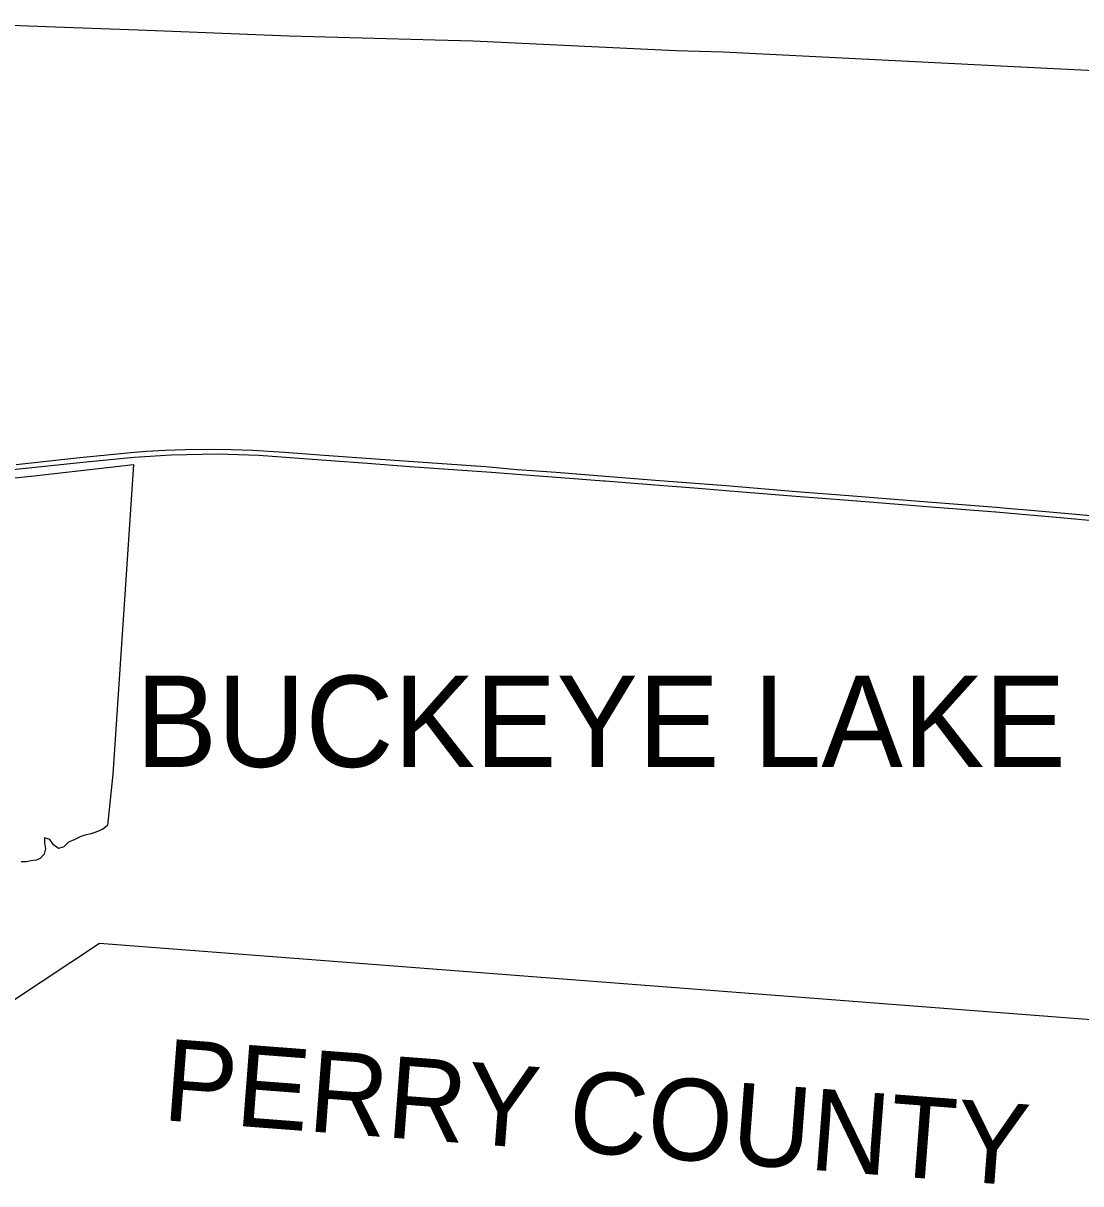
# Model space of a CAD drawing. Extents: x 1853412 to 2125412, y 78841 to 855418.
# Drawn here: x 1977959 to 1990925, y 700118 to 714345 of the extents above; entities that cross this region are included whole.
import ezdxf

# ---------------------------------------------------------------- set-up
doc = ezdxf.new("R2010")
doc.units = 0
for name, color, linetype in [('GM_X_Corporation', 7, 'Continuous'), ('GM_X_Corporation_Text', 7, 'Continuous'), ('GM_X_County', 7, 'Continuous'), ('GM_X_County_Text', 7, 'Continuous'), ('GM_X_US_Route', 7, 'Continuous'), ('UT_P_Electric', 7, 'Continuous')]:
    doc.layers.add(name, color=color, linetype=linetype)

msp = doc.modelspace()

# ---------------------------------------------------------------- linework, layer by layer
at = {"layer": 'GM_X_Corporation'}
msp.add_lwpolyline([(1976528, 708641), (1978057, 708794), (1979311, 708937), (1979058, 705139), (1978993, 704509), (1978936, 704465), (1978868, 704437), (1978792, 704409), (1978716, 704390), (1978664, 704374), (1978590, 704338), (1978514, 704306), (1978456, 704250), (1978390, 704227), (1978330, 704273), (1978286, 704337), (1978220, 704359), (1978218, 704297), (1978234, 704225), (1978216, 704159), (1978167, 704107), (1978117, 704085), (1978052, 704076), (1978000, 704064), (1977932, 704064)], dxfattribs=at)
at = {"layer": 'GM_X_County'}
msp.add_lwpolyline([(1991425, 702099), (1978895, 703062), (1976042, 701178), (1970119, 701527), (1969837, 701546), (1969206, 701588), (1968963, 701604), (1967601, 701695), (1967104, 701729), (1966807, 701761), (1966648, 701765), (1966605, 701765), (1965937, 701808), (1964838, 701880), (1963273, 701974), (1962141, 702051), (1961404, 702092), (1960067, 702149), (1959325, 702195), (1956245, 702403), (1956176, 702427), (1945541, 702974)], dxfattribs=at)
at = {"layer": 'GM_X_US_Route'}
for p, q in [((1990352, 713802), (1990516, 713794)), ((1990516, 713794), (1991173, 713761))]:
    msp.add_line(p, q, dxfattribs=at)
for points in [[(1977155, 714345), (1977251, 714341), (1978575, 714294), (1979368, 714263)], [(1979368, 714263), (1979686, 714252), (1981219, 714192), (1983008, 714140), (1983474, 714129), (1985961, 714010), (1986539, 713992), (1990352, 713802)]]:
    msp.add_lwpolyline(points, dxfattribs=at)
at = {"layer": 'UT_P_Electric'}
for p, q in [((1984497, 708781), (1985078, 708737)), ((1985701, 708688), (1986186, 708649))]:
    msp.add_line(p, q, dxfattribs=at)
for points in [[(1977266, 708814), (1977909, 708884), (1978729, 708968), (1979319, 709027), (1979773, 709055), (1980339, 709065), (1980848, 709048), (1981728, 708986), (1982178, 708950), (1982699, 708912)], [(1977873, 708936), (1978652, 709022), (1979028, 709060), (1979323, 709088), (1979472, 709098), (1979701, 709113), (1979946, 709120), (1980266, 709123), (1980510, 709120), (1980775, 709111), (1981164, 709085), (1981648, 709049), (1982105, 709017), (1982626, 708979), (1983628, 708910), (1984015, 708876), (1984491, 708840), (1985099, 708792), (1985658, 708748)], [(1982699, 708912), (1983701, 708843), (1984011, 708817), (1984497, 708781)], [(1985078, 708737), (1985094, 708736), (1985653, 708692), (1985701, 708688)], [(1985658, 708748), (1985816, 708736), (1986578, 708676), (1987438, 708606), (1988083, 708554), (1988895, 708491), (1989889, 708412), (1990064, 708397), (1990312, 708374), (1991182, 708300), (1992113, 708219), (1993316, 708115), (1994168, 708039), (1995118, 707960)], [(1986186, 708649), (1986572, 708618), (1987431, 708549), (1988077, 708497), (1988889, 708432), (1988984, 708425)], [(1988984, 708425), (1989882, 708355), (1990673, 708285)], [(1990673, 708285), (1991116, 708246), (1992051, 708165), (1993257, 708060), (1993312, 708056), (1993707, 708022)]]:
    msp.add_lwpolyline(points, dxfattribs=at)

# ---------------------------------------------------------------- texts
at = {"layer": 'GM_X_Corporation_Text'}
msp.add_text('BUCKEYE LAKE', height=1120, rotation=0, dxfattribs=at).set_placement((1979337, 705228))
at = {"layer": 'GM_X_County_Text'}
msp.add_text('PERRY COUNTY', height=1000, rotation=355.6219, dxfattribs=at).set_placement((1979655, 700900))

doc.saveas('drawing.dxf')
